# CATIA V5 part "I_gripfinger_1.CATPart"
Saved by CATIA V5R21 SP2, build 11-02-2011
Part number: I_gripfinger_1
Bounding box of the stored display mesh (mm): x -20 to 20, y -5 to 5, z 0 to 60
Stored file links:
  \\ariel.ad.iei.liu.se\LAB_DELMIA\A1_LAB_INTRO_2011\LAB_INTRO_DATA_2011\I_gripfinger_1.CATPart
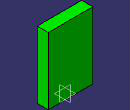
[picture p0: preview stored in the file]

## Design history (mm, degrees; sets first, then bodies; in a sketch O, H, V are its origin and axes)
Body1 (main body)
  Sketch1 on xy-plane, origin (0, 0, 0), H (1, 0, 0), V (0, 1, 0)
    line L1 (-20, -5) -> (20, -5)
    line L2 (20, -5) -> (20, 5)
    line L3 (20, 5) -> (-20, 5)
    line L4 (-20, 5) -> (-20, -5)
    horizontal: L1 H, L3 H
    vertical: L2 V, L4 V
  Pad1: profile Sketch1, direction (0, 0, 1), length 60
